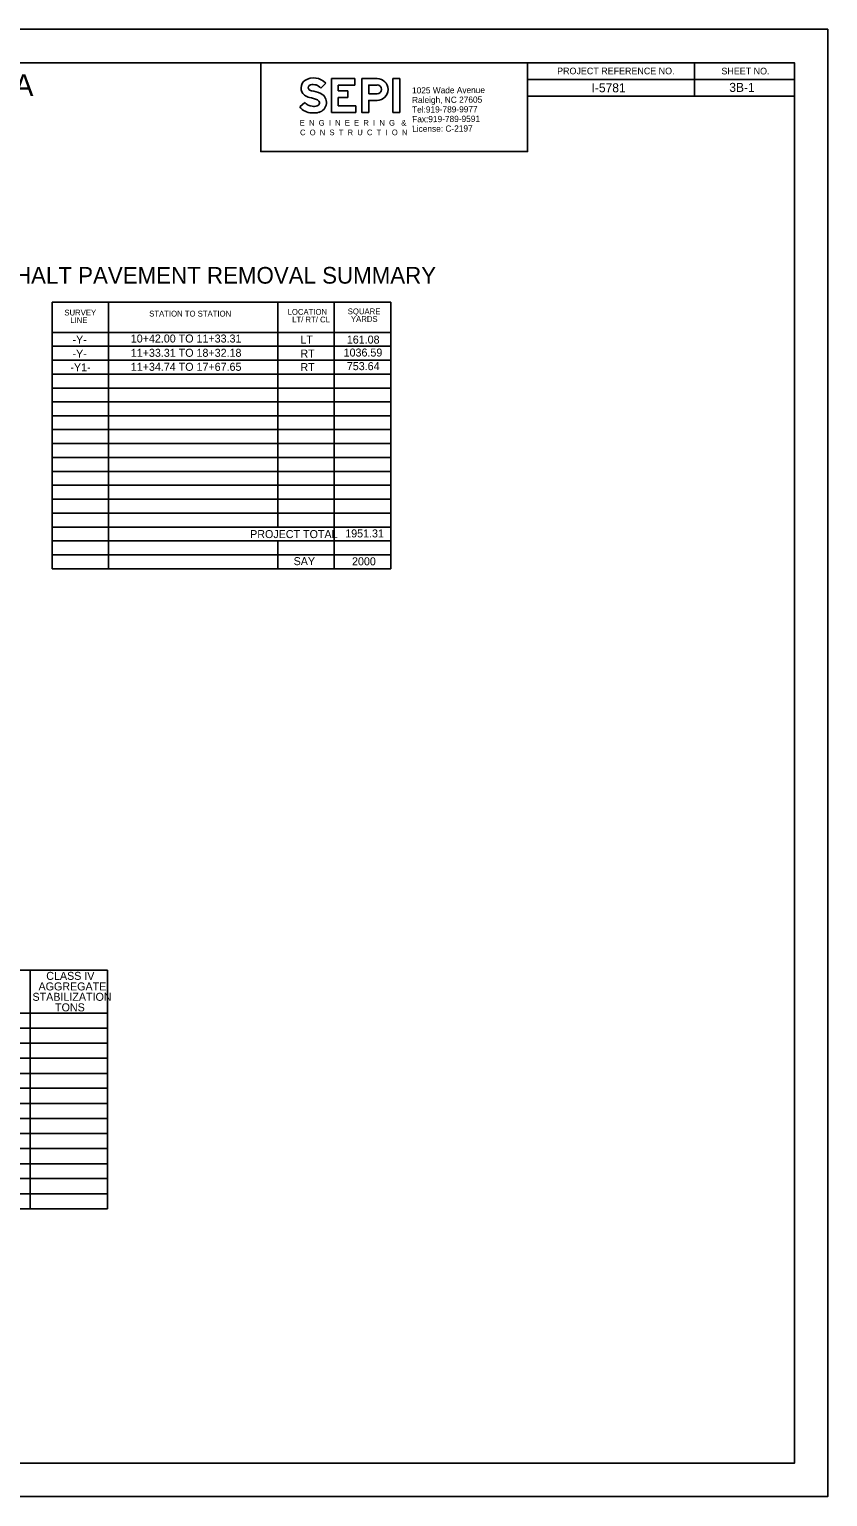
# Model space of a CAD drawing. Extents: x 573680 to 575380, y -53324 to -52224.
# Drawn here: x 574781 to 575380, y -53324 to -52224 of the extents above; entities that cross this region are included whole.
import ezdxf

# ---------------------------------------------------------------- set-up
doc = ezdxf.new("R2010")
doc.units = 0
for name, color, linetype in [('Old_Level_2', 7, 'Continuous'), ('Old_Level_58', 7, 'Continuous'), ('Old_Level_61', 7, 'Continuous'), ('Prop Dimension Text', 7, 'Continuous'), ('Sheet Data Field CELL', 7, 'Continuous'), ('Sheet Plan And Profile CELL', 7, 'Continuous'), ('Sheet Plot Border Outside CELL', 7, 'Continuous'), ('Sheet Summary Combination CELL', 7, 'Continuous'), ('Sheet Summary Combination Grid CELL', 7, 'Continuous')]:
    doc.layers.add(name, color=color, linetype=linetype)

msp = doc.modelspace()

# ---------------------------------------------------------------- linework, layer by layer
at = {"layer": 'Old_Level_58'}
msp.add_lwpolyline([(574954.8, -52249.3), (575154.8, -52249.3), (575154.8, -52316), (574954.8, -52316)], close=True, dxfattribs=at)
at = {"layer": 'Old_Level_61'}
for p, q in [((575003.5, -52264.7), (574999.9, -52268.3)), ((575007.7, -52286.6), (575007.7, -52261.1)), ((575007.7, -52261.1), (575025.4, -52261.1)), ((575025.4, -52266.1), (575012.8, -52266.1)), ((575012.8, -52266.1), (575012.8, -52270.5)), ((575012.8, -52270.5), (575020.1, -52270.5)), ((575020.1, -52270.5), (575020.1, -52275.5)), ((575025.4, -52261.1), (575025.4, -52266.1)), ((575042, -52261.1), (575030.5, -52261.1)), ((575053.9, -52261.1), (575059, -52261.1)), ((575053.9, -52286.6), (575053.9, -52261.1)), ((575059, -52261.1), (575059, -52286.6)), ((574984.1, -52282.4), (574987.8, -52279.1)), ((575020.1, -52275.5), (575012.8, -52275.5)), ((575012.8, -52275.5), (575012.8, -52281.7)), ((575012.8, -52281.7), (575026, -52281.7)), ((575026, -52281.7), (575026, -52286.6)), ((575042, -52272.6), (575035.7, -52272.6)), ((575026, -52286.6), (575007.7, -52286.6)), ((575059, -52286.6), (575053.9, -52286.6))]:
    msp.add_line(p, q, dxfattribs=at)
for points in [[(575030.5, -52261.1), (575042, -52261.1)], [(575042, -52277.6), (575035.7, -52277.6), (575035.7, -52286.6), (575030.5, -52286.6), (575030.5, -52261.1)], [(575030.5, -52261.1), (575030.5, -52286.6), (575035.7, -52286.6), (575035.7, -52277.6), (575042, -52277.6)], [(575035.7, -52272.6), (575035.7, -52266.1), (575042, -52266.1)], [(575035.7, -52272.6), (575035.7, -52266.1), (575042, -52266.1)], [(575042, -52272.6), (575035.7, -52272.6)]]:
    msp.add_lwpolyline(points, dxfattribs=at)
for centre, radius, start, end in [((574994.5, -52272.9), 12.2, 42.1326, 122.978), ((574992.1, -52268.2), 7.09, 127.7369, 229.6652), ((574992.5, -52268), 2.11, 103.5309, 215.5146), ((574993.6, -52266.4), 4.05, 224.8335, 256.8487), ((574994, -52273.5), 7.79, 41.6205, 105.1977), ((574986.2, -52305.1), 35.4, 67.2046, 79.386), ((575042, -52269.4), 8.26, 270.0084, 90.0084), ((575042, -52269.4), 8.26, 270.0084, 90.0084), ((575042, -52269.3), 3.29, 270.0084, 90.0084), ((575042, -52269.3), 3.29, 270.0084, 90.0084), ((574993.1, -52275.8), 11.2, 216.3694, 269.0231), ((574993.6, -52265.2), 10.4, 234.0274, 257.3507), ((574993.9, -52274.1), 7.95, 219.2142, 265.7728), ((574985.4, -52306.1), 31.3, 67.7855, 79.0603), ((574994.4, -52272.2), 9.88, 263.8471, 285.0484), ((574996.3, -52279.4), 2.46, 286.1133, 66.6482), ((574996.5, -52279.2), 7.55, 283.8986, 63.5915), ((574994.3, -52270.1), 16.9, 265.1338, 283.7744)]:
    msp.add_arc(centre, radius, start, end, dxfattribs=at)
at = {"layer": 'Sheet Plan And Profile CELL'}
for points in [[(575354.9, -52249.3), (573854.9, -52249.3), (573854.9, -53299.3), (575354.9, -53299.3)], [(575154.8, -52249.3), (575354.9, -52249.3), (575354.9, -52274.4), (575154.8, -52274.4)]]:
    msp.add_lwpolyline(points, close=True, dxfattribs=at)
at = {"layer": 'Sheet Plot Border Outside CELL'}
msp.add_lwpolyline([(573679.9, -53324.3), (575379.9, -53324.3), (575379.9, -52224.3), (573679.9, -52224.3)], close=True, dxfattribs=at)
at = {"layer": 'Sheet Summary Combination CELL'}
for p, q in [((575279.9, -52249.4), (575279.9, -52274.4)), ((575154.8, -52261.9), (575354.9, -52261.9)), ((575154.8, -52274.4), (575354.9, -52274.4)), ((574925.8, -52429), (574925.8, -52429)), ((574931.5, -52429), (574931.5, -52429)), ((574939.6, -52428.9), (574939.6, -52428.9)), ((574944.7, -52429), (574944.7, -52429))]:
    msp.add_line(p, q, dxfattribs=at)
msp.add_lwpolyline([(575154.8, -52249.3), (575354.9, -52249.3), (575354.9, -52274.4), (575154.8, -52274.4)], close=True, dxfattribs=at)
at = {"layer": 'Sheet Summary Combination Grid CELL'}
for p, q in [((574798.4, -52428.9), (575052.3, -52428.9)), ((574798.4, -52428.9), (574798.4, -52628.7)), ((574840.7, -52428.9), (574840.7, -52628.7)), ((574967.6, -52428.9), (574967.6, -52597.3)), ((575009.9, -52428.9), (575009.9, -52628.7)), ((575052.3, -52428.9), (575052.3, -52628.7)), ((574798.4, -52451.5), (575052.3, -52451.5)), ((574798.4, -52461.9), (575052.3, -52461.9)), ((574798.4, -52472.3), (575052.3, -52472.3)), ((574798.4, -52482.7), (575052.3, -52482.7)), ((574798.4, -52493.2), (575052.3, -52493.2)), ((574798.4, -52503.6), (575052.3, -52503.6)), ((574798.4, -52514), (575052.3, -52514)), ((574798.4, -52524.4), (575052.3, -52524.4)), ((574798.4, -52534.9), (575052.3, -52534.9)), ((574798.4, -52545.3), (575052.3, -52545.3)), ((574798.4, -52555.7), (575052.3, -52555.7)), ((574798.4, -52566.1), (575052.3, -52566.1)), ((574798.4, -52576.6), (575052.3, -52576.6)), ((574798.4, -52587), (575052.3, -52587)), ((574798.4, -52597.4), (575052.3, -52597.4)), ((574798.4, -52607.8), (575052.3, -52607.8)), ((574967.6, -52607.8), (574967.6, -52628.7)), ((574798.4, -52618.3), (575052.3, -52618.3)), ((574798.4, -52628.7), (575052.3, -52628.7)), ((574259.8, -52929.5), (574839.8, -52929.5)), ((574781.8, -52929.5), (574781.8, -53108.5)), ((574839.8, -52929.5), (574839.8, -53108.5)), ((574259.8, -52961.8), (574839.8, -52961.8)), ((574259.8, -52973.1), (574839.8, -52973.1)), ((574259.8, -52984.4), (574839.8, -52984.4)), ((574259.8, -52995.7), (574839.8, -52995.7)), ((574259.8, -53007), (574839.8, -53007)), ((574259.8, -53018.2), (574839.8, -53018.2)), ((574259.8, -53029.5), (574839.8, -53029.5)), ((574259.8, -53040.8), (574839.8, -53040.8)), ((574259.8, -53052.1), (574839.8, -53052.1)), ((574259.8, -53063.4), (574839.8, -53063.4)), ((574259.8, -53074.7), (574839.8, -53074.7)), ((574259.8, -53085.9), (574839.8, -53085.9)), ((574259.8, -53097.2), (574839.8, -53097.2)), ((574259.8, -53108.5), (574839.8, -53108.5))]:
    msp.add_line(p, q, dxfattribs=at)

# ---------------------------------------------------------------- texts
at = {"layer": 'Old_Level_2'}
for s, height, rotation, p in [('1025 Wade Avenue', 4.658, 0.3479, (575068.2, -52272.4)), ('Tel:919-789-9977 ', 4.658, 0.3479, (575068.2, -52286.8)), ('Raleigh, NC 27605', 4.658, 0.3479, (575068.2, -52279.6)), ('E  N  G  I  N  E  E  R  I  N  G   &', 4.25, 0.0085, (574984, -52296.5)), ('Fax:919-789-9591', 4.658, 0.3479, (575068.3, -52294)), ('C  O  N  S  T  R  U  C  T  I  O  N', 4.25, 0.0085, (574984.2, -52303.7)), ('License: C-2197', 4.658, 0.3479, (575068.3, -52301.2))]:
    msp.add_text(s, height=height, rotation=rotation, dxfattribs=at).set_placement(p)
at = {"layer": 'Prop Dimension Text'}
for s, p in [('-Y-', (574813.6, -52459.9)), ('10+42.00 TO 11+33.31', (574857.3, -52459.1)), ('LT', (574984.5, -52459.9)), ('161.08', (575019.3, -52459.9)), ('-Y-', (574813.6, -52470.5)), ('11+33.31 TO 18+32.18', (574857.3, -52469.8)), ('RT', (574984.5, -52470.4)), ('1036.59', (575016.9, -52469.6)), ('-Y1-', (574812, -52480.7)), ('11+34.74 TO 17+67.65', (574857.3, -52480.3)), ('RT', (574984.5, -52480.5)), ('753.64', (575019.3, -52479.8)), ('PROJECT TOTAL', (574946.8, -52605.7)), ('1951.31', (575018.1, -52605.2)), ('SAY', (574979.4, -52626)), ('2000', (575023.2, -52626.1))]:
    msp.add_text(s, height=6, dxfattribs=at).set_placement(p)
at = {"layer": 'Sheet Data Field CELL'}
for s, p in [('I-5781', (575202.8, -52271.5)), ('3B-1', (575306.1, -52271.2))]:
    msp.add_text(s, height=6.75, dxfattribs=at).set_placement(p)
at = {"layer": 'Sheet Plan And Profile CELL'}
for s, p in [('PROJECT REFERENCE NO.', (575177, -52258)), ('SHEET NO.', (575300.2, -52258.1))]:
    msp.add_text(s, height=5, rotation=360, dxfattribs=at).set_placement(p)
at = {"layer": 'Sheet Summary Combination CELL'}
for s, height, p in [('STATE OF NORTH CAROLINA', 16.25, (574477.6, -52274.2)), ('PROJECT REFERENCE NO.', 5, (575177, -52258)), ('SHEET NO.', 5, (575300.2, -52258.1)), ('SURVEY', 4.33, (574807.5, -52438.8)), ('STATION TO STATION', 4.332, (574871.1, -52439.6)), ('LOCATION', 4.33, (574974.9, -52438.3)), ('LINE', 4.33, (574811.9, -52444.5)), ('LT/ RT/ CL', 4.33, (574978.3, -52444))]:
    msp.add_text(s, height=height, dxfattribs=at).set_placement(p)
msp.add_text('ASPHALT PAVEMENT REMOVAL SUMMARY', height=12.5, rotation=0.0119, dxfattribs=at).set_placement((574737, -52415))
at = {"layer": 'Sheet Summary Combination Grid CELL'}
for s, height, p in [('SQUARE', 4.33, (575020, -52437.9)), ('YARDS', 4.33, (575022.4, -52443.6)), ('CLASS IV', 6, (574793.9, -52936.9)), ('AGGREGATE', 6, (574788.1, -52944.8)), ('STABILIZATION', 6, (574783.6, -52952.6)), ('TONS', 6, (574800.5, -52960.5))]:
    msp.add_text(s, height=height, dxfattribs=at).set_placement(p)

doc.saveas('drawing.dxf')
